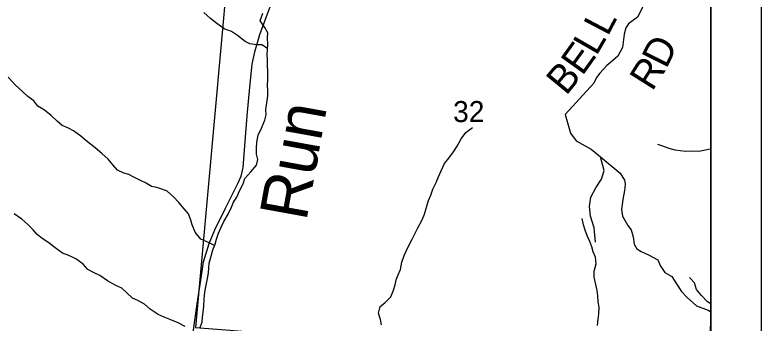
# Model space of a CAD drawing. Extents: x -13.1 to 43.1, y 0 to 22.
# Drawn here: x 7.517 to 9, y 16.837 to 17.45 of the extents above; entities that cross this region are included whole.
import ezdxf

# ---------------------------------------------------------------- set-up
doc = ezdxf.new("R2010")
doc.units = 0
for name, color, linetype in [('GM_X_Corporation', 7, 'Continuous'), ('GM_X_Minor_River', 7, 'Continuous'), ('GM_X_Minor_River_Text', 7, 'Continuous'), ('GM_X_Section_Text', 7, 'Continuous'), ('GM_X_State_Route', 7, 'Continuous'), ('GM_X_Township_Road', 7, 'Continuous'), ('GM_X_Township_Road_Text', 7, 'Continuous'), ('SH_Data', 7, 'Continuous')]:
    doc.layers.add(name, color=color, linetype=linetype)

msp = doc.modelspace()

# ---------------------------------------------------------------- linework, layer by layer
at = {"layer": 'GM_X_Corporation'}
for points in [[(8.9, 15.7487), (8.9, 20.9), (7.0804, 20.9), (7.0615, 20.6138), (7.0162, 19.896), (7.0106, 19.8452), (6.9616, 19.1692), (6.9507, 19.0184), (6.8365, 17.1257), (6.8234, 16.908), (6.7528, 15.9566), (7.8612, 15.855), (8.7782, 15.7572)], [(8.9, 15.7487), (8.9, 20.9), (7.0804, 20.9), (7.0615, 20.6138), (7.0162, 19.896), (7.0106, 19.8452), (6.9616, 19.1692), (6.9507, 19.0184), (6.8365, 17.1257), (6.8234, 16.908), (6.7528, 15.9566), (7.8612, 15.855), (8.7782, 15.7572)], [(8.9, 15.7481), (8.9, 20.9), (7.0807, 20.9), (7.0617, 20.6133), (7.0164, 19.8954), (7.0108, 19.8446), (6.9509, 19.0179), (6.8236, 16.9075), (6.7531, 15.956), (7.8614, 15.8545), (8.7784, 15.7567)], [(8.9, 16.8362), (8.9, 17.7183), (7.9639, 17.8036), (7.8759, 16.828), (7.9357, 16.8233), (8.8534, 16.7472), (8.8951, 16.7437)]]:
    msp.add_lwpolyline(points, close=True, dxfattribs=at)
at = {"layer": 'GM_X_Minor_River'}
for p, q in [((7.9055, 17.4429), (7.892, 17.4544)), ((7.9179, 17.4326), (7.9055, 17.4429)), ((7.9323, 17.4219), (7.9179, 17.4326)), ((7.9474, 17.4172), (7.9323, 17.4219)), ((7.9594, 17.4088), (7.9474, 17.4172)), ((7.9741, 17.3969), (7.9594, 17.4088)), ((7.9839, 17.3923), (7.9741, 17.3969)), ((7.9972, 17.3907), (7.9839, 17.3923)), ((8.0074, 17.3907), (7.9972, 17.3907)), ((8.0189, 17.3834), (8.0074, 17.3907)), ((7.5179, 17.3104), (7.5033, 17.326)), ((7.5318, 17.2974), (7.5179, 17.3104)), ((7.542, 17.2878), (7.5318, 17.2974)), ((7.554, 17.279), (7.542, 17.2878)), ((7.5623, 17.2684), (7.554, 17.279)), ((7.5755, 17.2607), (7.5623, 17.2684)), ((7.5883, 17.2496), (7.5755, 17.2607)), ((7.6003, 17.2385), (7.5883, 17.2496)), ((7.6105, 17.2301), (7.6003, 17.2385)), ((7.6229, 17.2247), (7.6105, 17.2301)), ((7.6328, 17.219), (7.6229, 17.2247)), ((8.4132, 17.2158), (8.4262, 17.226)), ((7.6478, 17.2086), (7.6328, 17.219)), ((7.6606, 17.1972), (7.6478, 17.2086)), ((8.404, 17.203), (8.4132, 17.2158)), ((7.6761, 17.1853), (7.6606, 17.1972)), ((8.396, 17.189), (8.404, 17.203)), ((7.6892, 17.1739), (7.6761, 17.1853)), ((8.3883, 17.1777), (8.396, 17.189)), ((8.805, 17.1886), (8.7948, 17.1921)), ((8.8171, 17.184), (8.805, 17.1886)), ((8.8295, 17.1805), (8.8171, 17.184)), ((8.8394, 17.1797), (8.8295, 17.1805)), ((8.8507, 17.1781), (8.8394, 17.1797)), ((8.8632, 17.1788), (8.8507, 17.1781)), ((8.8761, 17.1779), (8.8632, 17.1788)), ((8.8863, 17.1798), (8.8761, 17.1779)), ((8.8988, 17.1827), (8.8863, 17.1798)), ((8.9, 17.183), (8.8988, 17.1827)), ((7.702, 17.1628), (7.6892, 17.1739)), ((8.3704, 17.1543), (8.3795, 17.1648)), ((8.3795, 17.1648), (8.3883, 17.1777)), ((7.7122, 17.151), (7.702, 17.1628)), ((7.7208, 17.141), (7.7122, 17.151)), ((8.3638, 17.1395), (8.3704, 17.1543)), ((7.7329, 17.1353), (7.7208, 17.141)), ((7.7427, 17.1326), (7.7329, 17.1353)), ((8.3577, 17.1263), (8.3638, 17.1395)), ((7.7529, 17.1268), (7.7427, 17.1326)), ((7.7665, 17.1203), (7.7529, 17.1268)), ((7.7774, 17.1149), (7.7665, 17.1203)), ((8.3538, 17.1164), (8.3577, 17.1263)), ((7.788, 17.1084), (7.7774, 17.1149)), ((7.7986, 17.1064), (7.788, 17.1084)), ((7.8084, 17.1033), (7.7986, 17.1064)), ((8.3476, 17.1032), (8.3538, 17.1164)), ((7.819, 17.0991), (7.8084, 17.1033)), ((7.8321, 17.0876), (7.819, 17.0991)), ((8.3391, 17.0805), (8.3434, 17.0915)), ((8.3434, 17.0915), (8.3476, 17.1032)), ((7.8423, 17.0765), (7.8321, 17.0876)), ((7.8532, 17.0639), (7.8423, 17.0765)), ((8.3357, 17.0692), (8.3391, 17.0805)), ((7.8614, 17.0544), (7.8532, 17.0639)), ((8.3306, 17.0533), (8.3357, 17.0692)), ((7.53, 17.0437), (7.5153, 17.0544)), ((7.8663, 17.0415), (7.8614, 17.0544)), ((8.326, 17.0419), (8.3306, 17.0533)), ((8.6467, 17.0322), (8.6441, 17.0448)), ((7.5424, 17.0326), (7.53, 17.0437)), ((7.5526, 17.0223), (7.5424, 17.0326)), ((7.8692, 17.032), (7.8663, 17.0415)), ((7.8752, 17.0175), (7.8692, 17.032)), ((8.3179, 17.0264), (8.326, 17.0419)), ((8.65, 17.0216), (8.6467, 17.0322)), ((7.5608, 17.0127), (7.5526, 17.0223)), ((7.886, 17.0034), (7.8752, 17.0175)), ((8.3056, 17.0022), (8.3179, 17.0264)), ((8.6552, 17.0087), (8.65, 17.0216)), ((7.571, 17.0047), (7.5608, 17.0127)), ((7.5838, 16.9963), (7.571, 17.0047)), ((7.9012, 16.9972), (7.886, 17.0034)), ((8.2987, 16.9882), (8.3056, 17.0022)), ((8.6593, 16.9992), (8.6552, 17.0087)), ((7.5966, 16.9867), (7.5838, 16.9963)), ((7.6109, 16.9756), (7.5966, 16.9867)), ((7.9133, 16.9912), (7.9012, 16.9972)), ((8.2903, 16.9712), (8.2987, 16.9882)), ((8.6634, 16.9885), (8.6593, 16.9992)), ((8.666, 16.9786), (8.6634, 16.9885)), ((7.6238, 16.971), (7.6109, 16.9756)), ((7.6377, 16.9648), (7.6238, 16.971)), ((8.2856, 16.958), (8.2903, 16.9712)), ((8.6708, 16.968), (8.666, 16.9786)), ((7.652, 16.9537), (7.6377, 16.9648)), ((8.2829, 16.9436), (8.2856, 16.958)), ((8.6722, 16.9543), (8.6708, 16.968)), ((7.6614, 16.9434), (7.652, 16.9537)), ((7.6731, 16.9373), (7.6614, 16.9434)), ((8.2782, 16.933), (8.2829, 16.9436)), ((8.6684, 16.9403), (8.6722, 16.9543)), ((7.6852, 16.9311), (7.6731, 16.9373)), ((7.7006, 16.9208), (7.6852, 16.9311)), ((8.2748, 16.9228), (8.2782, 16.933)), ((8.6679, 16.9282), (8.6684, 16.9403)), ((8.6712, 16.9137), (8.6679, 16.9282)), ((8.8674, 16.917), (8.858, 16.9277)), ((7.7172, 16.9112), (7.7006, 16.9208)), ((7.7289, 16.9062), (7.7172, 16.9112)), ((8.2693, 16.9023), (8.2724, 16.9125)), ((8.2724, 16.9125), (8.2748, 16.9228)), ((8.6741, 16.9016), (8.6712, 16.9137)), ((8.8718, 16.9033), (8.8674, 16.917)), ((7.7387, 16.8974), (7.7289, 16.9062)), ((7.7504, 16.8863), (7.7387, 16.8974)), ((8.2639, 16.8891), (8.2693, 16.9023)), ((8.6756, 16.8906), (8.6741, 16.9016)), ((8.8816, 16.8915), (8.8718, 16.9033)), ((7.761, 16.8813), (7.7504, 16.8863)), ((8.2521, 16.877), (8.2639, 16.8891)), ((8.6762, 16.8792), (8.6756, 16.8906)), ((8.8932, 16.8793), (8.8816, 16.8915)), ((7.7742, 16.874), (7.761, 16.8813)), ((7.7854, 16.8641), (7.7742, 16.874)), ((8.2394, 16.8566), (8.2426, 16.8695)), ((8.2426, 16.8695), (8.2521, 16.877)), ((8.6781, 16.8682), (8.6762, 16.8792)), ((8.6776, 16.8545), (8.6781, 16.8682)), ((8.9, 16.8747), (8.8932, 16.8793)), ((7.8013, 16.8538), (7.7854, 16.8641)), ((7.813, 16.8484), (7.8013, 16.8538)), ((8.2431, 16.8437), (8.2394, 16.8566)), ((8.6764, 16.8447), (8.6776, 16.8545)), ((7.8266, 16.843), (7.813, 16.8484)), ((7.8413, 16.8372), (7.8266, 16.843)), ((7.8553, 16.8299), (7.8413, 16.8372)), ((8.2453, 16.8331), (8.2431, 16.8437)), ((8.6748, 16.8322), (8.6764, 16.8447))]:
    msp.add_line(p, q, dxfattribs=at)
msp.add_lwpolyline([(7.884, 16.8263), (7.889, 16.8388), (7.8898, 16.8486), (7.8907, 16.8581), (7.8919, 16.8706), (7.8928, 16.8847), (7.894, 16.8979), (7.8967, 16.9123), (7.8995, 16.9252), (7.9011, 16.9366), (7.9019, 16.9464), (7.9027, 16.9559), (7.907, 16.9699), (7.9098, 16.9824), (7.9144, 16.9937), (7.9171, 17.0036), (7.9214, 17.0153), (7.9267, 17.0278), (7.9317, 17.0388), (7.9402, 17.0535), (7.9471, 17.0671), (7.9513, 17.0773), (7.9575, 17.0875), (7.9632, 17.0996), (7.9702, 17.114), (7.9736, 17.1242), (7.9855, 17.1378), (7.9966, 17.1506), (7.9993, 17.162), (7.9971, 17.1726), (7.9968, 17.184), (7.9973, 17.1965), (8.0004, 17.2109), (8.0066, 17.2245), (8.0131, 17.2404), (8.0162, 17.251), (8.0152, 17.2616), (8.0172, 17.2749), (8.0191, 17.2889), (8.0192, 17.2988), (8.0185, 17.3094), (8.0194, 17.3223), (8.0195, 17.3371), (8.0188, 17.3496), (8.0189, 17.3606), (8.0182, 17.3709), (8.0187, 17.3807), (8.0195, 17.3913), (8.0188, 17.4046), (8.0197, 17.4145), (8.0137, 17.4251), (8.0043, 17.4381), (8.0094, 17.4536)], dxfattribs=at)
at = {"layer": 'GM_X_State_Route'}
msp.add_lwpolyline([(7.8635, 16.7717), (7.871, 16.818), (7.8791, 16.8748), (7.8872, 16.9309), (7.8916, 16.9589), (7.9025, 16.9948), (7.9138, 17.022), (7.9354, 17.0655), (7.9597, 17.1142), (7.9666, 17.1289), (7.9702, 17.1463), (7.9745, 17.1982), (7.9783, 17.2494), (7.9838, 17.3062), (7.9884, 17.3517), (7.9935, 17.3763), (8.0037, 17.4107), (8.0227, 17.4629), (8.0421, 17.5147), (8.0483, 17.5306)], dxfattribs=at)
at = {"layer": 'GM_X_Township_Road'}
for points in [[(8.7647, 17.4659), (8.7542, 17.4457), (8.7365, 17.4319), (8.7308, 17.4239), (8.7279, 17.4117), (8.7261, 17.3957), (8.7247, 17.3851), (8.7153, 17.3675), (8.7009, 17.3553), (8.6934, 17.3495), (8.6791, 17.3338), (8.6727, 17.3251), (8.6674, 17.314), (8.6105, 17.2517), (8.6211, 17.2145), (8.6322, 17.1991), (8.6623, 17.1826), (8.6806, 17.1675)], [(8.6708, 16.9978), (8.6684, 17.0259), (8.6606, 17.0497), (8.6586, 17.0687), (8.6618, 17.087), (8.6712, 17.1057), (8.6829, 17.1232), (8.6881, 17.1403), (8.6806, 17.1675)], [(8.6806, 17.1675), (8.72, 17.1348), (8.7285, 17.1212), (8.73, 17.1136), (8.7293, 17.1056), (8.7284, 17.1002)], [(8.7284, 17.1002), (8.7253, 17.0828), (8.7224, 17.0626), (8.7248, 17.0494), (8.7352, 17.0312), (8.7417, 17.0225), (8.7456, 17.0081), (8.748, 16.9937), (8.753, 16.9846), (8.7618, 16.9794), (8.7763, 16.9726), (8.7946, 16.9625), (8.7996, 16.9516), (8.8088, 16.9376), (8.8229, 16.9297), (8.8318, 16.915), (8.8421, 16.8995), (8.8529, 16.8874), (8.8716, 16.8708), (8.8948, 16.8623), (8.9, 16.859)]]:
    msp.add_lwpolyline(points, dxfattribs=at)
at = {"layer": 'SH_Data'}
for p, q in [((9, 21), (9, 14)), ((8.9, 20.9), (8.9, 14.1))]:
    msp.add_line(p, q, dxfattribs=at)

# ---------------------------------------------------------------- texts
at = {"layer": 'GM_X_Minor_River_Text'}
msp.add_text('Run', height=0.0947, rotation=79.7206, dxfattribs=at).set_placement((8.0957, 17.0376))
at = {"layer": 'GM_X_Section_Text'}
msp.add_text('32', height=0.04186, rotation=0, dxfattribs=at).set_placement((8.3877, 17.2366))
at = {"layer": 'GM_X_Township_Road_Text'}
for s, rotation, p in [('L', 62.2288, (8.6951, 17.4058)), ('L', 59.9579, (8.6726, 17.3669)), ('D', 63.4057, (8.8113, 17.3411)), ('E', 54.3064, (8.6445, 17.3272)), ('B', 50.5142, (8.6123, 17.2879)), ('R', 57.7985, (8.7835, 17.2964))]:
    msp.add_text(s, height=0.0568, rotation=rotation, dxfattribs=at).set_placement(p)

doc.saveas('drawing.dxf')
